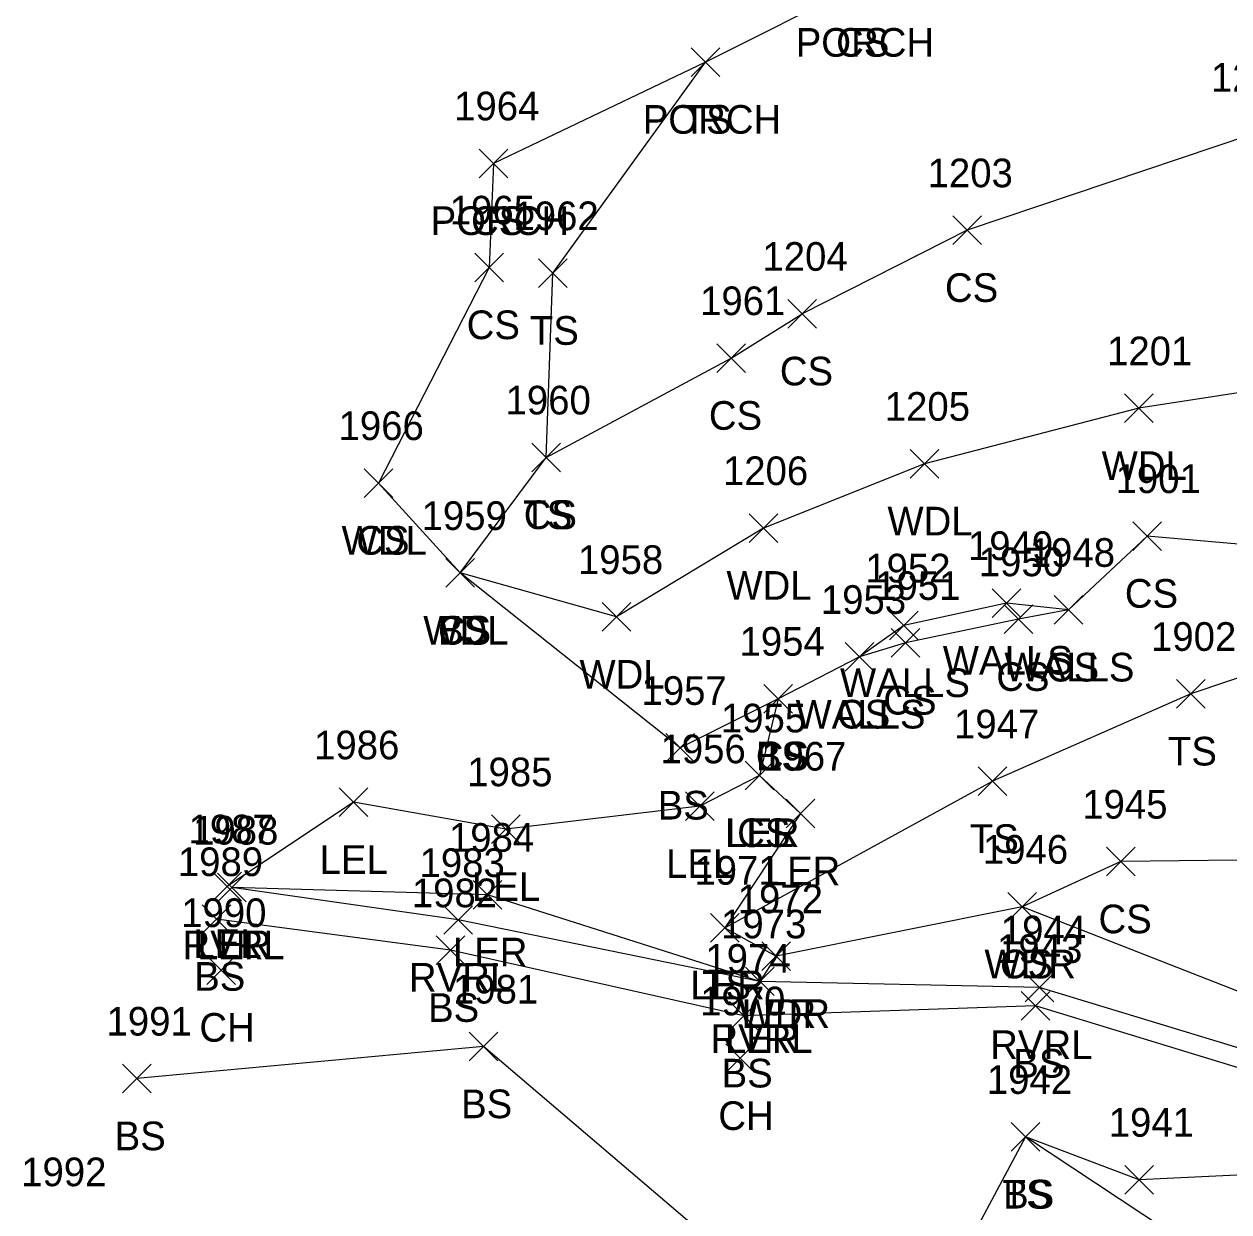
# Model space of a CAD drawing. Extents: x 1504228 to 1506103, y 437717 to 440106.
# Drawn here: x 1505051 to 1505135.1, y 438160.2 to 438243.1 of the extents above; entities that cross this region are included whole.
import ezdxf

# ---------------------------------------------------------------- set-up
doc = ezdxf.new("R2010")
doc.units = 0
for name, color, linetype in [('L_A', 7, 'Continuous'), ('L_I', 7, 'Continuous'), ('L_TIC', 7, 'Continuous'), ('LARO', 7, 'Continuous'), ('LAWA', 7, 'Continuous'), ('LAWE', 7, 'Continuous'), ('LBF', 7, 'Continuous'), ('LELB', 7, 'Continuous'), ('LWS', 7, 'Continuous')]:
    doc.layers.add(name, color=color, linetype=linetype)

msp = doc.modelspace()

# ---------------------------------------------------------------- linework, layer by layer
at = {"layer": 'L_TIC'}
for points in [[(1505097.567, 438239.478), (1505099.567, 438241.478)], [(1505099.567, 438239.478), (1505097.567, 438241.478)], [(1505097.567, 438239.478), (1505099.567, 438241.478)], [(1505099.567, 438239.478), (1505097.567, 438241.478)], [(1505082.767, 438232.411), (1505084.767, 438234.411)], [(1505084.767, 438232.411), (1505082.767, 438234.411)], [(1505082.767, 438232.411), (1505084.767, 438234.411)], [(1505084.767, 438232.411), (1505082.767, 438234.411)], [(1505115.834, 438227.742), (1505117.834, 438229.742)], [(1505117.834, 438227.742), (1505115.834, 438229.742)], [(1505082.463, 438225.145), (1505084.463, 438227.145)], [(1505084.463, 438225.145), (1505082.463, 438227.145)], [(1505086.904, 438224.749), (1505088.904, 438226.749)], [(1505088.904, 438224.749), (1505086.904, 438226.749)], [(1505104.312, 438221.915), (1505106.312, 438223.915)], [(1505106.312, 438221.915), (1505104.312, 438223.915)], [(1505099.361, 438218.82), (1505101.361, 438220.82)], [(1505101.361, 438218.82), (1505099.361, 438220.82)], [(1505127.791, 438215.321), (1505129.791, 438217.321)], [(1505129.791, 438215.321), (1505127.791, 438217.321)], [(1505086.443, 438211.89), (1505088.443, 438213.89)], [(1505088.443, 438211.89), (1505086.443, 438213.89)], [(1505086.443, 438211.89), (1505088.443, 438213.89)], [(1505088.443, 438211.89), (1505086.443, 438213.89)], [(1505112.846, 438211.449), (1505114.846, 438213.449)], [(1505114.846, 438211.449), (1505112.846, 438213.449)], [(1505074.759, 438210.103), (1505076.759, 438212.103)], [(1505076.759, 438210.103), (1505074.759, 438212.103)], [(1505074.759, 438210.103), (1505076.759, 438212.103)], [(1505076.759, 438210.103), (1505074.759, 438212.103)], [(1505101.61, 438206.96), (1505103.61, 438208.96)], [(1505103.61, 438206.96), (1505101.61, 438208.96)], [(1505128.385, 438206.402), (1505130.385, 438208.402)], [(1505130.385, 438206.402), (1505128.385, 438208.402)], [(1505080.457, 438203.829), (1505082.457, 438205.829)], [(1505082.457, 438203.829), (1505080.457, 438205.829)], [(1505080.457, 438203.829), (1505082.457, 438205.829)], [(1505082.457, 438203.829), (1505080.457, 438205.829)], [(1505080.457, 438203.829), (1505082.457, 438205.829)], [(1505082.457, 438203.829), (1505080.457, 438205.829)], [(1505118.58, 438201.732), (1505120.58, 438203.732)], [(1505120.58, 438201.732), (1505118.58, 438203.732)], [(1505122.884, 438201.256), (1505124.884, 438203.256)], [(1505124.884, 438201.256), (1505122.884, 438203.256)], [(1505122.884, 438201.256), (1505124.884, 438203.256)], [(1505124.884, 438201.256), (1505122.884, 438203.256)], [(1505091.358, 438200.76), (1505093.358, 438202.76)], [(1505093.358, 438200.76), (1505091.358, 438202.76)], [(1505119.414, 438200.601), (1505121.414, 438202.601)], [(1505121.414, 438200.601), (1505119.414, 438202.601)], [(1505111.409, 438200.168), (1505113.409, 438202.168)], [(1505113.409, 438200.168), (1505111.409, 438202.168)], [(1505111.531, 438198.947), (1505113.531, 438200.947)], [(1505113.531, 438198.947), (1505111.531, 438200.947)], [(1505108.307, 438197.975), (1505110.307, 438199.975)], [(1505110.307, 438197.975), (1505108.307, 438199.975)], [(1505108.307, 438197.975), (1505110.307, 438199.975)], [(1505110.307, 438197.975), (1505108.307, 438199.975)], [(1505131.424, 438195.394), (1505133.424, 438197.394)], [(1505133.424, 438195.394), (1505131.424, 438197.394)], [(1505102.635, 438195.053), (1505104.635, 438197.053)], [(1505104.635, 438195.053), (1505102.635, 438197.053)], [(1505102.635, 438195.053), (1505104.635, 438197.053)], [(1505104.635, 438195.053), (1505102.635, 438197.053)], [(1505095.792, 438191.624), (1505097.792, 438193.624)], [(1505097.792, 438191.624), (1505095.792, 438193.624)], [(1505101.335, 438189.702), (1505103.335, 438191.702)], [(1505103.335, 438189.702), (1505101.335, 438191.702)], [(1505101.335, 438189.702), (1505103.335, 438191.702)], [(1505103.335, 438189.702), (1505101.335, 438191.702)], [(1505101.335, 438189.702), (1505103.335, 438191.702)], [(1505103.335, 438189.702), (1505101.335, 438191.702)], [(1505117.601, 438189.29), (1505119.601, 438191.29)], [(1505119.601, 438189.29), (1505117.601, 438191.29)], [(1505073.006, 438187.827), (1505075.006, 438189.827)], [(1505075.006, 438187.827), (1505073.006, 438189.827)], [(1505097.177, 438187.549), (1505099.177, 438189.549)], [(1505099.177, 438187.549), (1505097.177, 438189.549)], [(1505104.19, 438187.038), (1505106.19, 438189.038)], [(1505106.19, 438187.038), (1505104.19, 438189.038)], [(1505083.635, 438185.944), (1505085.635, 438187.944)], [(1505085.635, 438185.944), (1505083.635, 438187.944)], [(1505126.547, 438183.687), (1505128.547, 438185.687)], [(1505128.547, 438183.687), (1505126.547, 438185.687)], [(1505064.19, 438181.959), (1505066.19, 438183.959)], [(1505066.19, 438181.959), (1505064.19, 438183.959)], [(1505064.507, 438181.877), (1505066.507, 438183.877)], [(1505066.507, 438181.877), (1505064.507, 438183.877)], [(1505064.507, 438181.877), (1505066.507, 438183.877)], [(1505066.507, 438181.877), (1505064.507, 438183.877)], [(1505082.359, 438181.373), (1505084.359, 438183.373)], [(1505084.359, 438181.373), (1505082.359, 438183.373)], [(1505119.67, 438180.542), (1505121.67, 438182.542)], [(1505121.67, 438180.542), (1505119.67, 438182.542)], [(1505119.67, 438180.542), (1505121.67, 438182.542)], [(1505121.67, 438180.542), (1505119.67, 438182.542)], [(1505063.451, 438179.678), (1505065.451, 438181.678)], [(1505065.451, 438179.678), (1505063.451, 438181.678)], [(1505080.308, 438179.613), (1505082.308, 438181.613)], [(1505082.308, 438179.613), (1505080.308, 438181.613)], [(1505098.918, 438179.075), (1505100.918, 438181.075)], [(1505100.918, 438179.075), (1505098.918, 438181.075)], [(1505098.918, 438179.075), (1505100.918, 438181.075)], [(1505100.918, 438179.075), (1505098.918, 438181.075)], [(1505079.769, 438177.505), (1505081.769, 438179.505)], [(1505081.769, 438177.505), (1505079.769, 438179.505)], [(1505102.508, 438177.085), (1505104.508, 438179.085)], [(1505104.508, 438177.085), (1505102.508, 438179.085)], [(1505102.508, 438177.085), (1505104.508, 438179.085)], [(1505104.508, 438177.085), (1505102.508, 438179.085)], [(1505063.764, 438176.121), (1505065.764, 438178.121)], [(1505065.764, 438176.121), (1505063.764, 438178.121)], [(1505101.347, 438175.333), (1505103.347, 438177.333)], [(1505103.347, 438175.333), (1505101.347, 438177.333)], [(1505101.347, 438175.333), (1505103.347, 438177.333)], [(1505103.347, 438175.333), (1505101.347, 438177.333)], [(1505120.865, 438174.913), (1505122.865, 438176.913)], [(1505122.865, 438174.913), (1505120.865, 438176.913)], [(1505120.603, 438173.613), (1505122.603, 438175.613)], [(1505122.603, 438173.613), (1505120.603, 438175.613)], [(1505100.25, 438172.927), (1505102.25, 438174.927)], [(1505102.25, 438172.927), (1505100.25, 438174.927)], [(1505082.072, 438170.783), (1505084.072, 438172.783)], [(1505084.072, 438170.783), (1505082.072, 438172.783)], [(1505099.975, 438169.961), (1505101.975, 438171.961)], [(1505101.975, 438169.961), (1505099.975, 438171.961)], [(1505057.9, 438168.546), (1505059.9, 438170.546)], [(1505059.9, 438168.546), (1505057.9, 438170.546)], [(1505119.89, 438164.479), (1505121.89, 438166.479)], [(1505121.89, 438164.479), (1505119.89, 438166.479)], [(1505119.89, 438164.479), (1505121.89, 438166.479)], [(1505121.89, 438164.479), (1505119.89, 438166.479)], [(1505127.828, 438161.493), (1505129.828, 438163.493)], [(1505129.828, 438161.493), (1505127.828, 438163.493)]]:
    msp.add_lwpolyline(points, dxfattribs=at)
at = {"layer": 'LARO'}
for points in [[(1505102.335, 438190.702), (1505098.177, 438188.549), (1505084.635, 438186.944), (1505074.006, 438188.827), (1505065.19, 438182.959)], [(1505102.335, 438190.702), (1505105.19, 438188.038), (1505099.918, 438180.075), (1505103.508, 438178.085), (1505102.347, 438176.333), (1505083.359, 438182.373), (1505065.507, 438182.877)]]:
    msp.add_lwpolyline(points, dxfattribs=at)
at = {"layer": 'LAWA'}
for points in [[(1505159.07, 438229.354), (1505145.848, 438218.953), (1505128.791, 438216.321), (1505113.846, 438212.449), (1505102.61, 438207.96), (1505092.358, 438201.76), (1505081.457, 438204.829), (1505075.759, 438211.103)], [(1505159.07, 438229.354), (1505152.451, 438206.672), (1505158.934, 438198.457), (1505155.948, 438184.653), (1505161.167, 438179.869), (1505162.413, 438170.533), (1505153.781, 438167.414), (1505148.603, 438168.433), (1505144.429, 438172.233), (1505120.67, 438181.542), (1505103.508, 438178.085)]]:
    msp.add_lwpolyline(points, dxfattribs=at)
at = {"layer": 'LAWE'}
msp.add_lwpolyline([(1505192.342, 438183.974), (1505183.193, 438182.526), (1505169.265, 438177.558), (1505163.184, 438169.103), (1505153.153, 438165.832), (1505148.603, 438168.433), (1505142.16, 438169.739), (1505121.865, 438175.913), (1505102.347, 438176.333), (1505081.308, 438180.613), (1505065.507, 438182.877)], dxfattribs=at)
at = {"layer": 'LBF'}
msp.add_lwpolyline([(1505103.964, 438256.562), (1505109.238, 438245.851), (1505098.567, 438240.478), (1505083.767, 438233.411)], dxfattribs=at)
at = {"layer": 'LELB'}
for points in [[(1505147.346, 438265.092), (1505151.295, 438258.904), (1505151.02, 438247.541), (1505156.466, 438234.619), (1505159.07, 438229.354), (1505161.306, 438207.965), (1505158.934, 438198.457), (1505143.439, 438200.103), (1505132.424, 438196.394), (1505118.601, 438190.29)], [(1505151.02, 438247.541), (1505136.605, 438235.405), (1505116.834, 438228.742), (1505105.312, 438222.915)], [(1505087.443, 438212.89), (1505087.904, 438225.749), (1505098.567, 438240.478)], [(1505083.767, 438233.411), (1505083.463, 438226.145), (1505075.759, 438211.103)], [(1505100.361, 438219.82), (1505105.312, 438222.915)], [(1505081.457, 438204.829), (1505087.443, 438212.89), (1505100.361, 438219.82)], [(1505152.451, 438206.672), (1505144.789, 438206.04), (1505129.385, 438207.402), (1505123.884, 438202.256), (1505120.414, 438201.601), (1505112.531, 438199.947), (1505109.307, 438198.975), (1505103.635, 438196.053), (1505102.335, 438190.702)], [(1505103.635, 438196.053), (1505096.792, 438192.624), (1505081.457, 438204.829)], [(1505099.918, 438180.075), (1505118.601, 438190.29)], [(1505152.55, 438183.805), (1505147.891, 438184.928), (1505127.547, 438184.687), (1505120.67, 438181.542)], [(1505190.754, 438180.051), (1505183.502, 438180.459), (1505172.002, 438176.044), (1505165.088, 438168.018), (1505153.497, 438163.2), (1505142.827, 438168.143), (1505121.603, 438174.613), (1505101.25, 438173.927), (1505080.769, 438178.505), (1505064.451, 438180.678)], [(1505103.639, 438154.246), (1505083.072, 438171.783), (1505058.9, 438169.546)], [(1505153.497, 438163.2), (1505141.943, 438163.117), (1505128.828, 438162.493), (1505120.89, 438165.479), (1505101.813, 438129.775)], [(1505137.265, 438154.64), (1505120.89, 438165.479)]]:
    msp.add_lwpolyline(points, dxfattribs=at)
at = {"layer": 'LWS'}
msp.add_lwpolyline([(1505123.884, 438202.256), (1505119.58, 438202.732), (1505112.409, 438201.168), (1505109.307, 438198.975)], dxfattribs=at)

# ---------------------------------------------------------------- texts
at = {"layer": 'L_A'}
for s, p in [('PORCH', (1505104.86, 438240.851)), ('CS', (1505107.679, 438240.851)), ('PORCH', (1505094.189, 438235.478)), ('TS', (1505096.977, 438235.478)), ('PORCH', (1505079.389, 438228.411)), ('CS', (1505082.208, 438228.411)), ('CS', (1505115.275, 438223.742)), ('CS', (1505081.904, 438221.145)), ('TS', (1505086.314, 438220.749)), ('CS', (1505103.753, 438217.915)), ('CS', (1505098.802, 438214.82)), ('WDL', (1505126.208, 438211.321)), ('TS', (1505085.853, 438207.89)), ('CS', (1505085.884, 438207.89)), ('WDL', (1505111.263, 438207.449)), ('WDL', (1505073.177, 438206.103)), ('CS', (1505074.2, 438206.103)), ('WDL', (1505100.027, 438202.96)), ('CS', (1505127.826, 438202.402)), ('WDL', (1505078.875, 438199.829)), ('CS', (1505079.898, 438199.829)), ('BS', (1505079.898, 438199.829)), ('WALLS', (1505115.123, 438197.732)), ('WALLS', (1505119.428, 438197.256)), ('CS', (1505122.325, 438197.256)), ('WDL', (1505089.775, 438196.76)), ('WALLS', (1505107.952, 438196.168)), ('CS', (1505118.855, 438196.601)), ('CS', (1505110.972, 438194.947)), ('WALLS', (1505104.851, 438193.975)), ('CS', (1505107.748, 438193.975)), ('TS', (1505130.834, 438191.394)), ('CS', (1505102.076, 438191.053)), ('BS', (1505102.076, 438191.053)), ('BS', (1505095.233, 438187.624)), ('LER', (1505099.918, 438185.702)), ('LEL', (1505099.973, 438185.702)), ('CS', (1505100.776, 438185.702)), ('TS', (1505117.01, 438185.29)), ('LEL', (1505071.644, 438183.827)), ('LEL', (1505095.815, 438183.549)), ('LER', (1505102.772, 438183.038)), ('LEL', (1505082.273, 438181.944)), ('CS', (1505125.988, 438179.687)), ('RVRL', (1505062.074, 438177.877)), ('LEL', (1505062.827, 438177.959)), ('LER', (1505063.09, 438177.877)), ('LER', (1505080.941, 438177.373)), ('WDR', (1505118.032, 438176.542)), ('CS', (1505119.111, 438176.542)), ('BS', (1505062.892, 438175.678)), ('RVRL', (1505077.875, 438175.613)), ('LER', (1505097.501, 438175.075)), ('TS', (1505098.327, 438175.075)), ('BS', (1505079.21, 438173.505)), ('WDR', (1505100.871, 438173.085)), ('LER', (1505101.091, 438173.085)), ('CH', (1505063.253, 438172.121)), ('RVRL', (1505098.914, 438171.333)), ('LER', (1505099.929, 438171.333)), ('RVRL', (1505118.432, 438170.913)), ('BS', (1505120.044, 438169.613)), ('BS', (1505099.691, 438168.927)), ('BS', (1505081.513, 438166.783)), ('CH', (1505099.463, 438165.961)), ('BS', (1505057.341, 438164.546)), ('TS', (1505119.299, 438160.479)), ('BS', (1505119.331, 438160.479))]:
    msp.add_text(s, height=2, dxfattribs=at).set_placement(p)
at = {"layer": 'L_I'}
for s, p in [('1202', (1505133.834, 438238.405)), ('1964', (1505081.027, 438236.411)), ('1964', (1505081.027, 438236.411)), ('1203', (1505114.063, 438231.742)), ('1965', (1505080.723, 438229.145)), ('1962', (1505085.164, 438228.749)), ('1204', (1505102.54, 438225.915)), ('1961', (1505098.188, 438222.82)), ('1201', (1505126.586, 438219.321)), ('1960', (1505084.616, 438215.89)), ('1960', (1505084.616, 438215.89)), ('1205', (1505111.074, 438215.449)), ('1966', (1505072.964, 438214.103)), ('1966', (1505072.964, 438214.103)), ('1206', (1505099.783, 438210.96)), ('1901', (1505127.18, 438210.402)), ('1959', (1505078.757, 438207.829)), ('1959', (1505078.757, 438207.829)), ('1959', (1505078.757, 438207.829)), ('1949', (1505116.879, 438205.732)), ('1958', (1505089.665, 438204.76)), ('1950', (1505117.634, 438204.601)), ('1948', (1505121.192, 438205.256)), ('1948', (1505121.192, 438205.256)), ('1952', (1505109.716, 438204.168)), ('1951', (1505110.405, 438202.947)), ('1953', (1505106.615, 438201.975)), ('1953', (1505106.615, 438201.975)), ('1954', (1505100.942, 438199.053)), ('1954', (1505100.942, 438199.053)), ('1902', (1505129.653, 438199.394)), ('1957', (1505094.099, 438195.624)), ('1955', (1505099.642, 438193.702)), ('1955', (1505099.642, 438193.702)), ('1955', (1505099.642, 438193.702)), ('1947', (1505115.908, 438193.29)), ('1986', (1505071.258, 438191.827)), ('1956', (1505095.429, 438191.549)), ('1967', (1505102.45, 438191.038)), ('1985', (1505081.942, 438189.944)), ('1945', (1505124.855, 438187.687)), ('1987', (1505062.497, 438185.959)), ('1988', (1505062.814, 438185.877)), ('1988', (1505062.814, 438185.877)), ('1984', (1505080.666, 438185.373)), ('1946', (1505117.922, 438184.542)), ('1946', (1505117.922, 438184.542)), ('1989', (1505061.75, 438183.678)), ('1983', (1505078.615, 438183.613)), ('1971', (1505097.792, 438183.075)), ('1971', (1505097.792, 438183.075)), ('1982', (1505078.076, 438181.505)), ('1972', (1505100.815, 438181.085)), ('1972', (1505100.815, 438181.085)), ('1990', (1505061.985, 438180.121)), ('1973', (1505099.654, 438179.333)), ('1973', (1505099.654, 438179.333)), ('1944', (1505119.172, 438178.913)), ('1974', (1505098.557, 438176.927)), ('1943', (1505118.91, 438177.613)), ('1981', (1505080.946, 438174.783)), ('1970', (1505098.195, 438173.961)), ('1991', (1505056.774, 438172.546)), ('1942', (1505118.197, 438168.479)), ('1942', (1505118.197, 438168.479)), ('1941', (1505126.702, 438165.493)), ('1992', (1505050.819, 438162.037)), ('1992', (1505050.819, 438162.037))]:
    msp.add_text(s, height=2, dxfattribs=at).set_placement(p)

doc.saveas('drawing.dxf')
